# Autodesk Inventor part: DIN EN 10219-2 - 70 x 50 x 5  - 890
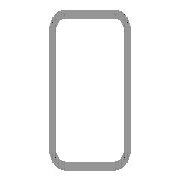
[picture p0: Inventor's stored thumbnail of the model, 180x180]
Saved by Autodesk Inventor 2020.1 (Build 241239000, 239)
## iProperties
Created: 2019-01
Part Number: DIN EN 10219-2 - 70 x 50 x 5  - 890
Material: Stahl, weich
Description: Kaltgeformte, geschweißte Baustahl-Hohlprofile aus unlegiertem Feinkorn-Baustahl
Document SubType Name: Modeling
Standard: DIN
Designer: lutzd
Standard Revision: 2006-07
Standards Organization: DIN
Language: de-DE
Size Designation: 70 x 50 x 5
Categories: <MemberInstance><Categories><Category DisplayName="Profile" InternalName="089c4875-fa83-4c05-b084-43b9cc11f5ed" Mnemonic="GRDR"><CategoryParameter DisplayName="
Stock Number: 70 x 50 x 5
Mass: 7223.98 g
Surface Area: 3709.07 cm^2
Volume: 920.252 cm^3
Density: 7.85 g/cm^3
Appearance: Halbpoliert
IsCustomPart: 1
_CCFamilyMember: 17
_CCFamilyDisplayName: DIN EN 10219-2 (Rechteckiges Hohlprofil - Kaltgeformt) - Kaltgeformte, geschweißte Baustahl-Hohlprofile aus unlegiertem Feinkorn-Baustahl
_FrameMemberDoc: Frame Member File
_Version: 15.0.0
_GetPNFromCC: 1
G_L: 890,000 mm
G_W: 50,000 mm
G_H: 70,000 mm
DocNumber: ADSK-014135
Folder: .
Dimensions: 50x70x890 mm
Mass: 7,224 kg
+55817728-7D80-4C04-8CFE-5699C75598A1+SCHNITTDETAIL1: Schnittwinkel 90,00 grd
+7F83CC26-C3BF-484F-8821-2DDBDAB4BD35+SCHNITTDETAIL2: Schnittwinkel 90,00 grd
Title: Profil-Bauteil
Author: lutzd
Revision Number: -
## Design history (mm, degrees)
node "Startebene"
node "Endebene"
sketch "Skizze"
  geometry: L1 (-25, -25)-(-25, 25); L2 (-15, 35)-(15, 35); L3 (25, 25)-(25, -25); L4 (15, -35)-(-15, -35); L5 (-15, 30)-(15, 30); L6 (20, 25)-(20, -25); L7 (15, -30)-(-15, -30); L8 (-20, -25)-(-20, 25); L9 (0, 51.899)-(0, -51.899) reference; L10 (-37.899, 0)-(37.899, 0) reference; A1 r 10 centre (-15, -25) between (-25, -25) and (-15, -35); A2 r 10 centre (-15, 25) between (-15, 35) and (-25, 25); A3 r 10 centre (15, 25) between (25, 25) and (15, 35); A4 r 10 centre (15, -25) between (15, -35) and (25, -25); A5 r 5 centre (-15, 25) between (-15, 30) and (-20, 25); A6 r 5 centre (15, 25) between (20, 25) and (15, 30); A7 r 5 centre (15, -25) between (15, -30) and (20, -25); A8 r 5 centre (-15, -25) between (-20, -25) and (-15, -30)
  constraints: 16 end point, 16 point on circle, 8 centre point, 8 tangent, 4 parallel, 3 equal radius, 2 perpendicular, 7 other
  dimensions: "d7" = 10 radius of A1 (= G_IR); "d10" = 70 distance between parallel lines of L2 L4 (= G_H); "d11" = 50 distance between parallel lines of L1 L3 (= G_W); "d12" = 5 distance between parallel lines of L3 L6 (= G_T); "d15" = 35 distance between parallel lines of L2 L10 (= 0.5 x d10); "d16" = 25 distance between parallel lines of L9 L3 (= 0.5 x d11)
extrude "Körper" new body sketch "Skizze" stored distance "d3" = 890 (= G_L); taper "d4" = 0 deg
node "Driven Length"
  sketch "Sketch3"
    geometry: L1 (0, 0)-(10, 0) reference
    constraints: 2 end point, 1 horizontal
  workplane "Work Plane3"
  sketch "Sketch4"
    geometry: L1 (-2, 50)-(12, 50) reference; L2 (-2, 940)-(12, 940) reference
    dimensions: "d18" = 890 distance between parallel lines of L1 L2 (derived)
workplane "Arbeitsebene4"
feature "Trennen1"
workplane "Arbeitsebene5"
feature "Trennen2"
sketch "Skizze5"
  geometry: L1 (-30, 0)-(0, 0) reference; L2 (-15, 0)-(-15, 288); 5 further points
  constraints: 3 point on line, 2 end point, 1 coincident, 1 midpoint, 1 vertical
  dimensions: "d19" = 60 distance of L2.start point (-15, 60); "d21" = 76 distance of point (-15, 288) point (-15, 212); "d22" = 76 distance of point (-15, 136) point (-15, 212) (= d21); "d23" = 76 distance of point (-15, 60) point (-15, 136) (= d21)
hole "Bohrung1" sketch "Skizze5" at (-15, 288), (-15, 212), (-15, 60), (-15, 136) diameter "d24" = 8.376; stored, may be unused: countersink angle "d28" = 90 deg, drill point angle "d30" = 0 deg; dims "d25" = 20, "d26" = 4, "d27" = 2, "d29" = 27.3
sketch "Skizze6"
  geometry: L1 (0, -50)-(0, 0) reference; L2 (0, 10)-(890, 10) reference; L3 (0, -28)-(183.5, -28); 2 further points
  constraints: 3 end point, 2 point on line, 1 horizontal
  dimensions: "d31" = 38 distance between parallel lines of L2 L3; "d32" = 118.5 distance from line of L1 point (118.5, -28); "d33" = 65 distance of point (118.5, -28) L3.end
hole "Bohrung2" sketch "Skizze6" at (118.5, -28), (183.5, -28) diameter "d34" = 6.647; stored, may be unused: countersink angle "d38" = 90 deg, drill point angle "d40" = 118 deg; dims "d35" = 16, "d36" = 4, "d37" = 2, "d39" = 8
body "Solid1"
other parameters: "G_W" = 50 [user parameter; used in 1 equation term], "G_H" = 70 [user parameter; used in 1 equation term], "G_T" = 5 [user parameter; used in 1 equation term], "G_IR" = 10 [user parameter; used in 1 equation term], "G_L" = 890 (= d18) [user parameter; used in 1 equation term], "G_OFFSET_END" = -25 [user parameter; used in 1 equation term], "B_L" = 965 [user parameter; used in 1 equation term], "d17" = 90 deg, "d20" = 76
